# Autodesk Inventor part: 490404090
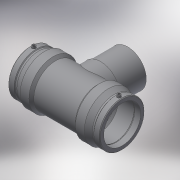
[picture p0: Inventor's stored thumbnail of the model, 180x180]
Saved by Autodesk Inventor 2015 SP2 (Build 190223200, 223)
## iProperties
Created: 2017-06
Part Number: 490404090
Material: Generic
Description: PLASSON TEE 90-90-90
Document SubType Name: Modeling
Designer: KIM
Mass: 1069.49 g
Surface Area: 2300.36 cm^2
Volume: 1069.49 cm^3
Density: 1 g/cm^3
Appearance: Default
Author: KIM
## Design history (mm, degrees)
derived "490404.ipt"
feature "Solid1::490404.ipt"
tag "TaggingFeature1"
body "Solid1"
other parameters: "d0" = 294, "d2" = 113, "d3" = 71, "d4" = 73.5, "d5" = 101.7, "d6" = 85.5, "d8" = 168 deg, "d10" = 28.4, "d11" = 9.46667, "d13" = 294, "d14" = 17.6296, "d17" = 81, "d19" = 3.52592, "d20" = 168 deg, "d22" = 105.09, "d23" = 113, "d24" = 101.9373, "d25" = 135 deg, "d26" = 205.8, "d27" = 135 deg, "d29" = 71, "d30" = 15, "d31" = 117.6, "d34" = 5 deg, "d35" = 15, "d39" = 5 deg, "d40" = 9.6, "d41" = 4.8, "d42" = 6, "d43" = 0, "d45" = 4, "d46" = 14, "d47" = 0, "d48" = -137, "d51" = 0, "d52" = 72, "d54" = 0, "d55" = 101.7, "d56" = 113, "d57" = 102.9, "d58" = 135 deg, "d59" = 71, "d60" = 71, "d61" = 135 deg, "d62" = 137, "d72" = 133.77, "d73" = 66.885, "d74" = -137, "d75" = 94.5, "d77" = 0, "d78" = 72, "d80" = 0, "d82" = 80.5, "d83" = 0, "d84" = 3, "d85" = 0, "d86" = 3, "d87" = 0, "d88" = 20.59, "d89" = 5.1475, "d90" = 20.59, "L_" = 294, "L_1" = 71, "D_" = 113, "A_" = 71, "d_2" = 12, "H_" = 137
